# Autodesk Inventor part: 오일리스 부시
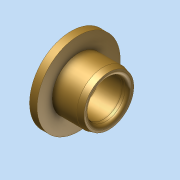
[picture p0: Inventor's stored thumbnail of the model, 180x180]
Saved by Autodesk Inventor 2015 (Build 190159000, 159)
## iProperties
Created: 2024-05
Part Number: 오일리스 부시
Material: 일반
Document SubType Name: Modeling
Designer: Administrator
Density: 1 g/cm^3
Appearance: 기본값
Author: Administrator
Author: jhkim
Creation Date: 2024-05-07
Sending System: Autodesk Inventor 2025
Preprocessor: ST-DEVELOPER v20
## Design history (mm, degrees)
node "오일리스 부시1"
node "솔리드1"
node "기준1"
